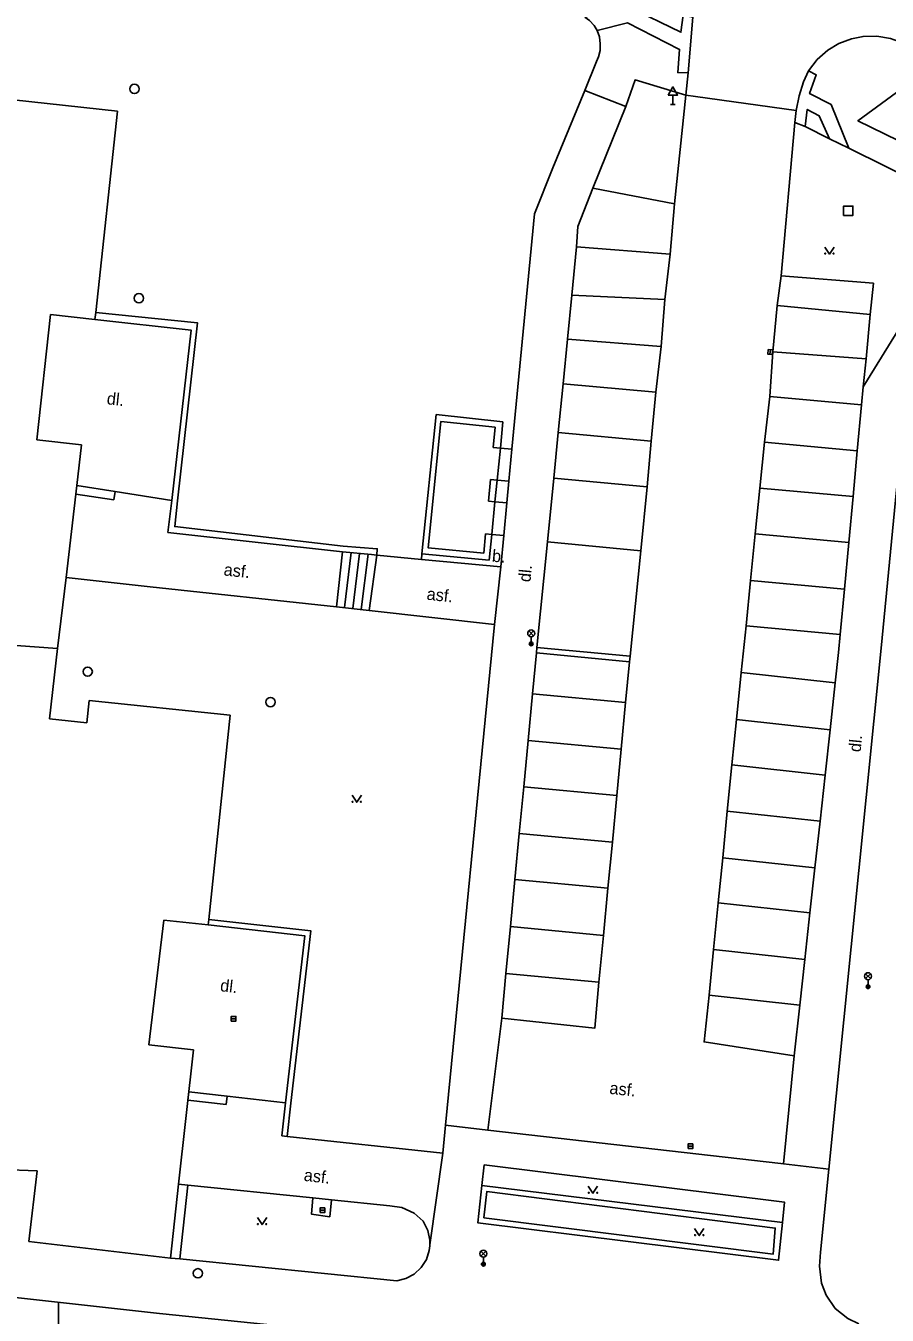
# Model space of a CAD drawing. Extents: x -602419 to -601554, y -1162937 to -1162362.
# Drawn here: x -602216.4 to -602170.3, y -1162637 to -1162567.9 of the extents above; entities that cross this region are included whole.
import ezdxf

# ---------------------------------------------------------------- set-up
doc = ezdxf.new("R2010")
doc.units = 0
doc.layers.add('Podklad', color=7, linetype='Continuous')

msp = doc.modelspace()

# ---------------------------------------------------------------- linework, layer by layer
at = {"layer": 'Podklad'}
for p, q in [((-602181.74, -1162571.631), (-602181.74, -1162572.14)), ((-602181.865, -1162572.14), (-602181.615, -1162572.14)), ((-602176.5185, -1162585.2755), (-602176.5415, -1162585.5245)), ((-602189.4625, -1162600.61), (-602189.1975, -1162600.345)), ((-602189.4625, -1162600.345), (-602189.1975, -1162600.61)), ((-602189.33, -1162600.665), (-602189.33, -1162601.04)), ((-602171.4225, -1162618.9799), (-602171.1575, -1162618.7149)), ((-602171.4225, -1162618.7149), (-602171.1575, -1162618.9799)), ((-602171.29, -1162619.0349), (-602171.29, -1162619.4099)), ((-602205.395, -1162621.13), (-602205.145, -1162621.13)), ((-602180.925, -1162627.96), (-602180.675, -1162627.96)), ((-602200.635, -1162631.39), (-602200.385, -1162631.39)), ((-602192.0225, -1162633.85), (-602191.7575, -1162633.585)), ((-602192.0225, -1162633.585), (-602191.7575, -1162633.85)), ((-602191.89, -1162633.905), (-602191.89, -1162634.28))]:
    msp.add_line(p, q, dxfattribs=at)
for points in [[(-602186.46, -1162567.45), (-602184.11, -1162566.9099), (-602181.31, -1162568.27), (-602181.2, -1162567.35), (-602180.67, -1162567.45)], [(-602186.46, -1162567.45), (-602186.21, -1162567.63), (-602185.96, -1162567.9), (-602185.8, -1162568.18)], [(-602180.67, -1162567.45), (-602180.93, -1162570.44)], [(-602185.8, -1162568.18), (-602185.68, -1162568.52), (-602185.63, -1162568.88), (-602185.64, -1162569.24), (-602185.73, -1162569.59), (-602185.84, -1162569.84)], [(-602185.8, -1162568.18), (-602184.17, -1162567.76), (-602181.38, -1162569.19), (-602181.48, -1162570.43), (-602180.93, -1162570.44)], [(-602174.48, -1162570.34), (-602174.02, -1162569.73), (-602173.45, -1162569.23), (-602172.85, -1162568.87), (-602172.17, -1162568.62), (-602171.56, -1162568.49), (-602170.82, -1162568.48), (-602170.08, -1162568.61), (-602169.31, -1162568.89)], [(-602169.31, -1162568.89), (-602167.5, -1162569.84), (-602171.83, -1162573.01), (-602169.67, -1162574.07), (-602155.45, -1162581.23), (-602140.7199, -1162588.61), (-602128.9699, -1162594.49), (-602127.26, -1162595.32), (-602122.9, -1162592.1599), (-602121.46, -1162592.84)], [(-602186.45, -1162571.38), (-602185.84, -1162569.84)], [(-602175.2199, -1162573.1), (-602175.14, -1162572.46), (-602174.98, -1162571.68), (-602174.74, -1162570.93), (-602174.48, -1162570.34)], [(-602172.32, -1162574.48), (-602173.27, -1162572.14), (-602174.42, -1162571.55), (-602174.06, -1162570.55), (-602174.48, -1162570.34)], [(-602181.04, -1162571.64), (-602183.77, -1162570.82), (-602184.27, -1162572.25)], [(-602180.93, -1162570.44), (-602181.04, -1162571.64)], [(-602219.04, -1162571.68), (-602211.48, -1162572.5)], [(-602188.17, -1162575.54), (-602186.45, -1162571.38)], [(-602186.45, -1162571.38), (-602184.27, -1162572.25)], [(-602181.65, -1162577.46), (-602181.04, -1162571.64)], [(-602175.14, -1162572.46), (-602180.5271, -1162571.7102), (-602181.04, -1162571.64)], [(-602184.27, -1162572.25), (-602186.02, -1162576.62)], [(-602173.36, -1162573.9699), (-602173.9, -1162572.74), (-602174.55, -1162572.4), (-602174.6599, -1162573.32)], [(-602211.48, -1162572.5), (-602212.65, -1162583.28)], [(-602175.95, -1162581.32), (-602175.2199, -1162573.1)], [(-602174.6599, -1162573.32), (-602175.2199, -1162573.1)], [(-602173.36, -1162573.9699), (-602174.6599, -1162573.32)], [(-602172.32, -1162574.48), (-602173.36, -1162573.9699)], [(-602165.69, -1162577.79), (-602170.33, -1162575.46), (-602172.32, -1162574.48)], [(-602188.17, -1162575.54), (-602189.1599, -1162578), (-602190.36, -1162590.61)], [(-602186.02, -1162576.62), (-602186.84, -1162578.68), (-602186.9, -1162579.76)], [(-602181.65, -1162577.46), (-602186.02, -1162576.62)], [(-602181.89, -1162580.1599), (-602181.65, -1162577.46)], [(-602165.69, -1162577.79), (-602171.55, -1162587.26)], [(-602186.9, -1162579.76), (-602187.1599, -1162582.35)], [(-602186.9, -1162579.76), (-602181.89, -1162580.1599)], [(-602173.61, -1162579.775), (-602173.36, -1162580.15), (-602173.11, -1162579.775)], [(-602181.89, -1162580.1599), (-602182.18, -1162582.59)], [(-602176.15, -1162582.9099), (-602175.95, -1162581.32)], [(-602171.17, -1162583.39), (-602171, -1162581.7199), (-602175.95, -1162581.32)], [(-602187.1599, -1162582.35), (-602187.39, -1162584.7199)], [(-602182.18, -1162582.59), (-602187.1599, -1162582.35)], [(-602182.18, -1162582.59), (-602182.37, -1162585.1)], [(-602215.08, -1162583.39), (-602215.8, -1162590.11)], [(-602212.69, -1162583.65), (-602215.08, -1162583.39)], [(-602212.65, -1162583.28), (-602212.69, -1162583.65)], [(-602212.65, -1162583.28), (-602207.2, -1162583.83), (-602208.27, -1162593.38), (-602208.42, -1162594.76), (-602199.4, -1162595.81), (-602197.57, -1162595.94), (-602197.6, -1162596.29)], [(-602176.39, -1162585.4), (-602176.15, -1162582.9099)], [(-602176.15, -1162582.9099), (-602171.17, -1162583.39)], [(-602171.4, -1162585.76), (-602171.17, -1162583.39)], [(-602212.69, -1162583.65), (-602207.54, -1162584.23), (-602208.58, -1162593.35)], [(-602187.39, -1162584.7199), (-602187.62, -1162587.1)], [(-602182.37, -1162585.1), (-602187.39, -1162584.7199)], [(-602182.37, -1162585.1), (-602182.6599, -1162587.56)], [(-602176.55, -1162587.79), (-602176.39, -1162585.4)], [(-602176.39, -1162585.4), (-602171.4, -1162585.76)], [(-602171.55, -1162587.26), (-602171.4, -1162585.76)], [(-602187.62, -1162587.1), (-602187.88, -1162589.71)], [(-602182.6599, -1162587.56), (-602187.62, -1162587.1)], [(-602182.6599, -1162587.56), (-602182.9099, -1162590.18)], [(-602171.64, -1162588.24), (-602171.55, -1162587.26)], [(-602176.84, -1162590.23), (-602176.55, -1162587.79)], [(-602176.55, -1162587.79), (-602171.64, -1162588.24)], [(-602171.87, -1162590.69), (-602171.64, -1162588.24)], [(-602195.18, -1162596.2199), (-602194.4099, -1162588.75)], [(-602194.4099, -1162588.75), (-602190.84, -1162589.15)], [(-602191.78, -1162595.14), (-602191.87, -1162596.18), (-602194.84, -1162595.9), (-602194.1599, -1162589.12), (-602191.26, -1162589.43), (-602191.36, -1162590.52)], [(-602190.84, -1162589.15), (-602190.98, -1162590.55)], [(-602215.8, -1162590.11), (-602213.42, -1162590.37)], [(-602213.42, -1162590.37), (-602213.67, -1162592.56), (-602214.24, -1162597.48)], [(-602187.88, -1162589.71), (-602188.12, -1162592.1599)], [(-602182.9099, -1162590.18), (-602187.88, -1162589.71)], [(-602182.9099, -1162590.18), (-602183.12, -1162592.63)], [(-602177.08, -1162592.69), (-602176.84, -1162590.23)], [(-602176.84, -1162590.23), (-602171.87, -1162590.69)], [(-602191.36, -1162590.52), (-602190.98, -1162590.55)], [(-602190.98, -1162590.55), (-602191.15, -1162592.26)], [(-602190.98, -1162590.55), (-602190.36, -1162590.61)], [(-602190.36, -1162590.61), (-602190.52, -1162592.32)], [(-602173.39, -1162629.19), (-602170.59, -1162601.27), (-602169.53, -1162590.4)], [(-602172.09, -1162593.14), (-602171.87, -1162590.69)], [(-602191.62, -1162593.4), (-602191.51, -1162592.23)], [(-602191.51, -1162592.23), (-602191.15, -1162592.26)], [(-602191.15, -1162592.26), (-602191.27, -1162593.43)], [(-602191.15, -1162592.26), (-602190.52, -1162592.32)], [(-602190.52, -1162592.32), (-602190.63, -1162593.49)], [(-602188.12, -1162592.1599), (-602188.46, -1162595.58)], [(-602183.12, -1162592.63), (-602188.12, -1162592.1599)], [(-602211.68, -1162593.32), (-602213.7199, -1162593.01), (-602213.67, -1162592.56)], [(-602211.61, -1162592.88), (-602213.67, -1162592.56)], [(-602211.61, -1162592.88), (-602211.68, -1162593.32)], [(-602208.58, -1162593.35), (-602211.61, -1162592.88)], [(-602183.12, -1162592.63), (-602183.46, -1162596.06)], [(-602177.33, -1162595.15), (-602177.08, -1162592.69)], [(-602177.08, -1162592.69), (-602172.09, -1162593.14)], [(-602172.32, -1162595.61), (-602172.09, -1162593.14)], [(-602208.58, -1162593.35), (-602208.78, -1162595.07), (-602199.43, -1162596.11), (-602197.89, -1162596.26), (-602197.6, -1162596.29)], [(-602191.27, -1162593.43), (-602191.62, -1162593.4)], [(-602191.27, -1162593.43), (-602191.44, -1162595.18)], [(-602190.63, -1162593.49), (-602191.27, -1162593.43)], [(-602190.63, -1162593.49), (-602190.8, -1162595.23)], [(-602191.44, -1162595.18), (-602191.78, -1162595.14)], [(-602191.44, -1162595.18), (-602191.58, -1162596.56)], [(-602190.8, -1162595.23), (-602191.44, -1162595.18)], [(-602190.8, -1162595.23), (-602190.96, -1162596.92)], [(-602177.58, -1162597.65), (-602177.33, -1162595.15)], [(-602177.33, -1162595.15), (-602172.32, -1162595.61)], [(-602188.46, -1162595.58), (-602189.02, -1162601.23)], [(-602183.46, -1162596.06), (-602188.46, -1162595.58)], [(-602172.55, -1162598.11), (-602172.32, -1162595.61)], [(-602199.43, -1162596.11), (-602199.76, -1162599.05)], [(-602199.33, -1162599.1), (-602198.9699, -1162596.15)], [(-602198.52, -1162596.2), (-602198.89, -1162599.15)], [(-602198.44, -1162599.2), (-602198.06, -1162596.24)], [(-602197.6, -1162596.29), (-602198, -1162599.25)], [(-602197.6, -1162596.29), (-602195.2, -1162596.52)], [(-602195.18, -1162596.2199), (-602195.2, -1162596.52)], [(-602195.2, -1162596.52), (-602190.96, -1162596.92)], [(-602191.58, -1162596.56), (-602195.18, -1162596.2199)], [(-602183.46, -1162596.06), (-602184.03, -1162601.7)], [(-602190.96, -1162596.92), (-602191.29, -1162600)], [(-602214.24, -1162597.48), (-602214.69, -1162601.29)], [(-602214.24, -1162597.48), (-602209.73, -1162597.98), (-602199.76, -1162599.05), (-602198, -1162599.25), (-602191.29, -1162600)], [(-602177.82, -1162600.07), (-602177.58, -1162597.65)], [(-602177.58, -1162597.65), (-602172.55, -1162598.11)], [(-602172.78, -1162600.54), (-602172.55, -1162598.11)], [(-602191.29, -1162600), (-602193.9099, -1162626.84)], [(-602178.08, -1162602.57), (-602177.82, -1162600.07)], [(-602177.82, -1162600.07), (-602172.78, -1162600.54)], [(-602214.69, -1162601.29), (-602222.34, -1162600.73)], [(-602173.05, -1162603.13), (-602172.87, -1162601.51), (-602172.78, -1162600.54)], [(-602214.69, -1162601.29), (-602215.12, -1162605.06)], [(-602189.02, -1162601.23), (-602189.05, -1162601.52)], [(-602184.03, -1162601.7), (-602189.02, -1162601.23)], [(-602189.05, -1162601.52), (-602189.26, -1162603.7199)], [(-602189.05, -1162601.52), (-602184.06, -1162602)], [(-602184.06, -1162602), (-602184.28, -1162604.19)], [(-602184.06, -1162602), (-602184.03, -1162601.7)], [(-602178.33, -1162605.09), (-602178.08, -1162602.57)], [(-602178.08, -1162602.57), (-602173.05, -1162603.13)], [(-602173.32, -1162605.64), (-602173.05, -1162603.13)], [(-602213.13, -1162605.27), (-602213.01, -1162604.08)], [(-602213.01, -1162604.08), (-602205.45, -1162604.86)], [(-602189.26, -1162603.7199), (-602189.5, -1162606.21)], [(-602184.28, -1162604.19), (-602189.26, -1162603.7199)], [(-602184.28, -1162604.19), (-602184.52, -1162606.68)], [(-602205.45, -1162604.86), (-602206.59, -1162615.81)], [(-602215.12, -1162605.06), (-602213.13, -1162605.27)], [(-602178.59, -1162607.53), (-602178.33, -1162605.09)], [(-602178.33, -1162605.09), (-602173.32, -1162605.64)], [(-602189.5, -1162606.21), (-602189.7199, -1162608.7)], [(-602184.52, -1162606.68), (-602189.5, -1162606.21)], [(-602173.59, -1162608.08), (-602173.32, -1162605.64)], [(-602184.52, -1162606.68), (-602184.74, -1162609.17)], [(-602178.83, -1162610), (-602178.59, -1162607.53)], [(-602178.59, -1162607.53), (-602173.59, -1162608.08)], [(-602173.86, -1162610.55), (-602173.59, -1162608.08)], [(-602189.7199, -1162608.7), (-602189.9699, -1162611.2)], [(-602184.74, -1162609.17), (-602189.7199, -1162608.7)], [(-602198.92, -1162609.155), (-602198.67, -1162609.53), (-602198.42, -1162609.155)], [(-602184.74, -1162609.17), (-602184.98, -1162611.67)], [(-602179.07, -1162612.5), (-602178.83, -1162610)], [(-602178.83, -1162610), (-602173.86, -1162610.55)], [(-602174.14, -1162613.05), (-602173.86, -1162610.55)], [(-602189.9699, -1162611.2), (-602190.2, -1162613.6599)], [(-602184.98, -1162611.67), (-602189.9699, -1162611.2)], [(-602184.98, -1162611.67), (-602185.2199, -1162614.13)], [(-602179.32, -1162614.92), (-602179.07, -1162612.5)], [(-602179.07, -1162612.5), (-602174.14, -1162613.05)], [(-602174.4, -1162615.46), (-602174.14, -1162613.05)], [(-602190.2, -1162613.6599), (-602190.44, -1162616.19)], [(-602185.2199, -1162614.13), (-602190.2, -1162613.6599)], [(-602185.2199, -1162614.13), (-602185.45, -1162616.67)], [(-602179.56, -1162617.42), (-602179.32, -1162614.92)], [(-602179.32, -1162614.92), (-602174.4, -1162615.46)], [(-602209.01, -1162615.85), (-602209.81, -1162622.52)], [(-602206.62, -1162616.1), (-602209.01, -1162615.85)], [(-602206.59, -1162615.81), (-602206.62, -1162616.1)], [(-602202.4, -1162627.43), (-602202.2, -1162625.6599), (-602201.13, -1162616.42), (-602206.59, -1162615.81)], [(-602174.68, -1162617.96), (-602174.4, -1162615.46)], [(-602206.62, -1162616.1), (-602201.46, -1162616.68), (-602202.48, -1162625.63)], [(-602190.44, -1162616.19), (-602190.68, -1162618.7)], [(-602185.45, -1162616.67), (-602190.44, -1162616.19)], [(-602185.45, -1162616.67), (-602185.7, -1162619.17)], [(-602179.8, -1162619.87), (-602179.56, -1162617.42)], [(-602179.56, -1162617.42), (-602174.68, -1162617.96)], [(-602174.95, -1162620.4), (-602174.68, -1162617.96)], [(-602190.68, -1162618.7), (-602190.9, -1162621.09)], [(-602185.7, -1162619.17), (-602190.68, -1162618.7)], [(-602185.7, -1162619.17), (-602185.93, -1162621.64), (-602190.9, -1162621.09)], [(-602175.25, -1162623.11), (-602180.07, -1162622.37), (-602179.8, -1162619.87)], [(-602179.8, -1162619.87), (-602174.95, -1162620.4)], [(-602175.25, -1162623.11), (-602174.95, -1162620.4)], [(-602190.9, -1162621.09), (-602191.6599, -1162627.1)], [(-602209.81, -1162622.52), (-602207.42, -1162622.79)], [(-602207.42, -1162622.79), (-602208.21, -1162629.99)], [(-602175.81, -1162628.9099), (-602175.25, -1162623.11)], [(-602205.61, -1162625.28), (-602207.67, -1162625.05), (-602207.7199, -1162625.5)], [(-602205.6599, -1162625.73), (-602207.7199, -1162625.5)], [(-602205.6599, -1162625.73), (-602205.61, -1162625.28)], [(-602202.48, -1162625.63), (-602205.61, -1162625.28)], [(-602202.48, -1162625.63), (-602202.68, -1162627.4), (-602202.4, -1162627.43)], [(-602193.9099, -1162626.84), (-602194.06, -1162628.34)], [(-602193.9099, -1162626.84), (-602191.6599, -1162627.1)], [(-602202.4, -1162627.43), (-602194.06, -1162628.34)], [(-602191.6599, -1162627.1), (-602175.96, -1162628.89)], [(-602194.76, -1162633.2399), (-602194.06, -1162628.34)], [(-602191.9699, -1162630.06), (-602191.85, -1162628.95)], [(-602191.85, -1162628.95), (-602175.76, -1162630.96), (-602175.87, -1162632.04)], [(-602175.96, -1162628.89), (-602175.81, -1162628.9099)], [(-602175.81, -1162628.9099), (-602173.39, -1162629.19)], [(-602215.78, -1162629.28), (-602217.69, -1162629.2)], [(-602216.23, -1162633.06), (-602215.78, -1162629.28)], [(-602173.39, -1162629.19), (-602173.83, -1162633.63)], [(-602208.21, -1162629.99), (-602208.65, -1162633.95)], [(-602207.7199, -1162630.04), (-602208.21, -1162629.99)], [(-602207.7199, -1162630.04), (-602208.15, -1162634)], [(-602201.02, -1162630.73), (-602207.7199, -1162630.04)], [(-602175.87, -1162632.04), (-602176.08, -1162634.07), (-602192.19, -1162632.06), (-602191.9699, -1162630.06)], [(-602191.9699, -1162630.06), (-602175.87, -1162632.04)], [(-602191.86, -1162631.8), (-602191.71, -1162630.39), (-602176.26, -1162632.35), (-602176.37, -1162633.74), (-602191.86, -1162631.8)], [(-602186.27, -1162630.105), (-602186.02, -1162630.48), (-602185.77, -1162630.105)], [(-602201.02, -1162630.73), (-602201.1, -1162631.6), (-602200.12, -1162631.74), (-602200.03, -1162630.84)], [(-602200.03, -1162630.84), (-602201.02, -1162630.73)], [(-602196.9, -1162631.1599), (-602200.03, -1162630.84)], [(-602196.9, -1162631.1599), (-602196.26, -1162631.25), (-602195.59, -1162631.54), (-602195.12, -1162631.98), (-602194.87, -1162632.48), (-602194.76, -1162632.99), (-602194.76, -1162633.29), (-602194.79, -1162633.55), (-602194.94, -1162634.03), (-602195.23, -1162634.46), (-602195.6, -1162634.81), (-602196.05, -1162635.04), (-602196.53, -1162635.17)], [(-602203.99, -1162631.7849), (-602203.74, -1162632.1599), (-602203.49, -1162631.7849)], [(-602180.58, -1162632.375), (-602180.33, -1162632.75), (-602180.08, -1162632.375)], [(-602243.69, -1162633.15), (-602236.7, -1162633.87), (-602209.24, -1162636.93), (-602196.53, -1162638.23), (-602179.79, -1162639.94)], [(-602208.65, -1162633.95), (-602216.23, -1162633.06)], [(-602173.83, -1162633.63), (-602173.89, -1162634.39), (-602173.79, -1162635.3), (-602173.54, -1162635.94), (-602173.05, -1162636.65), (-602172.37, -1162637.19), (-602171.78, -1162637.48)], [(-602208.65, -1162633.95), (-602208.15, -1162634)], [(-602208.15, -1162634), (-602196.53, -1162635.17)], [(-602214.6395, -1162636.3283), (-602214.623, -1162638.9659), (-602214.5247, -1162653.5672)]]:
    msp.add_lwpolyline(points, dxfattribs=at)
for points in [[(-602181.99, -1162571.631), (-602181.49, -1162571.631), (-602181.74, -1162571.198)], [(-602172.6, -1162578.08), (-602172.1, -1162578.08), (-602172.1, -1162577.58), (-602172.6, -1162577.58)], [(-602176.643, -1162585.264), (-602176.666, -1162585.513), (-602176.417, -1162585.536), (-602176.394, -1162585.287)], [(-602205.395, -1162621.255), (-602205.145, -1162621.255), (-602205.145, -1162621.005), (-602205.395, -1162621.005)], [(-602180.925, -1162628.085), (-602180.675, -1162628.085), (-602180.675, -1162627.835), (-602180.925, -1162627.835)], [(-602200.635, -1162631.515), (-602200.385, -1162631.515), (-602200.385, -1162631.265), (-602200.635, -1162631.265)]]:
    msp.add_lwpolyline(points, close=True, dxfattribs=at)
for centre, radius in [((-602210.58, -1162571.3), 0.25), ((-602173.5851, -1162580.1249), 0.025), ((-602173.1354, -1162580.1249), 0.025), ((-602210.34, -1162582.52), 0.25), ((-602189.33, -1162600.4775), 0.1875), ((-602189.33, -1162601.04), 0.1), ((-602189.33, -1162601.04), 0.0723), ((-602189.33, -1162601.04), 0.0438), ((-602213.08, -1162602.53), 0.25), ((-602203.29, -1162604.1599), 0.25), ((-602198.8951, -1162609.5049), 0.025), ((-602198.4454, -1162609.5049), 0.025), ((-602171.29, -1162618.8474), 0.1875), ((-602171.29, -1162619.4099), 0.1), ((-602171.29, -1162619.4099), 0.0723), ((-602171.29, -1162619.4099), 0.0438), ((-602186.2451, -1162630.4549), 0.025), ((-602185.7954, -1162630.4549), 0.025), ((-602203.9651, -1162632.1348), 0.025), ((-602203.5154, -1162632.1348), 0.025), ((-602180.5551, -1162632.7249), 0.025), ((-602180.1054, -1162632.7249), 0.025), ((-602191.89, -1162633.7175), 0.1875), ((-602207.18, -1162634.77), 0.25), ((-602191.89, -1162634.28), 0.1), ((-602191.89, -1162634.28), 0.0723), ((-602191.89, -1162634.28), 0.0438)]:
    msp.add_circle(centre, radius, dxfattribs=at)

# ---------------------------------------------------------------- texts
for s, rotation, p in [('dl.', 353.84, (-602212.08, -1162588.2)), ('b.', 354.56, (-602191.45, -1162596.63)), ('asf.', 353.84, (-602205.82, -1162597.37)), ('dl.', 84.59, (-602189.37, -1162597.75)), ('asf.', 353.84, (-602194.95, -1162598.67)), ('dl.', 84.32, (-602171.69, -1162606.86)), ('dl.', 353.4, (-602206.01, -1162619.65)), ('asf.', 353.96, (-602185.1599, -1162625.15)), ('asf.', 353.4, (-602201.53, -1162629.81))]:
    msp.add_text(s, height=0.65, rotation=rotation, dxfattribs=at).set_placement(p)

doc.saveas('drawing.dxf')
